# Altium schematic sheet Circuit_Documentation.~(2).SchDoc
size 431 x 279 mm; Date: Not shown in title block; ApprovedBy: Not shown in title block; CheckedBy: Not shown in title block; Author: Not shown in title block; CompanyName: Not shown in title block; Engineer: Not shown in title block; Organization: Not shown in title block; Address1: Not shown in title block; Address2: Not shown in title block; Address3: Not shown in title block; Address4: Not shown in title block; DocumentNumber: 1; Revision: Use project parameter SCH_Rev; SheetNumber: 1; SheetTotal: 2; PageSetup: Record=PageOptions¦CenterHorizontal=True¦CenterVertical=True¦PrintScale=1.00¦XCorrection=1.00¦YCorrection=1.00¦PrintKind=0¦BorderSize=5000000¦LeftOffset=0¦BottomOffset=0¦Orientation=2¦PaperLength=1000¦PaperWidth=1000¦Scale=100¦PaperSource=15¦PrintQuality=600¦MediaType=1¦DitherType=10¦PaperKind=Letter¦PrintScaleMode=1
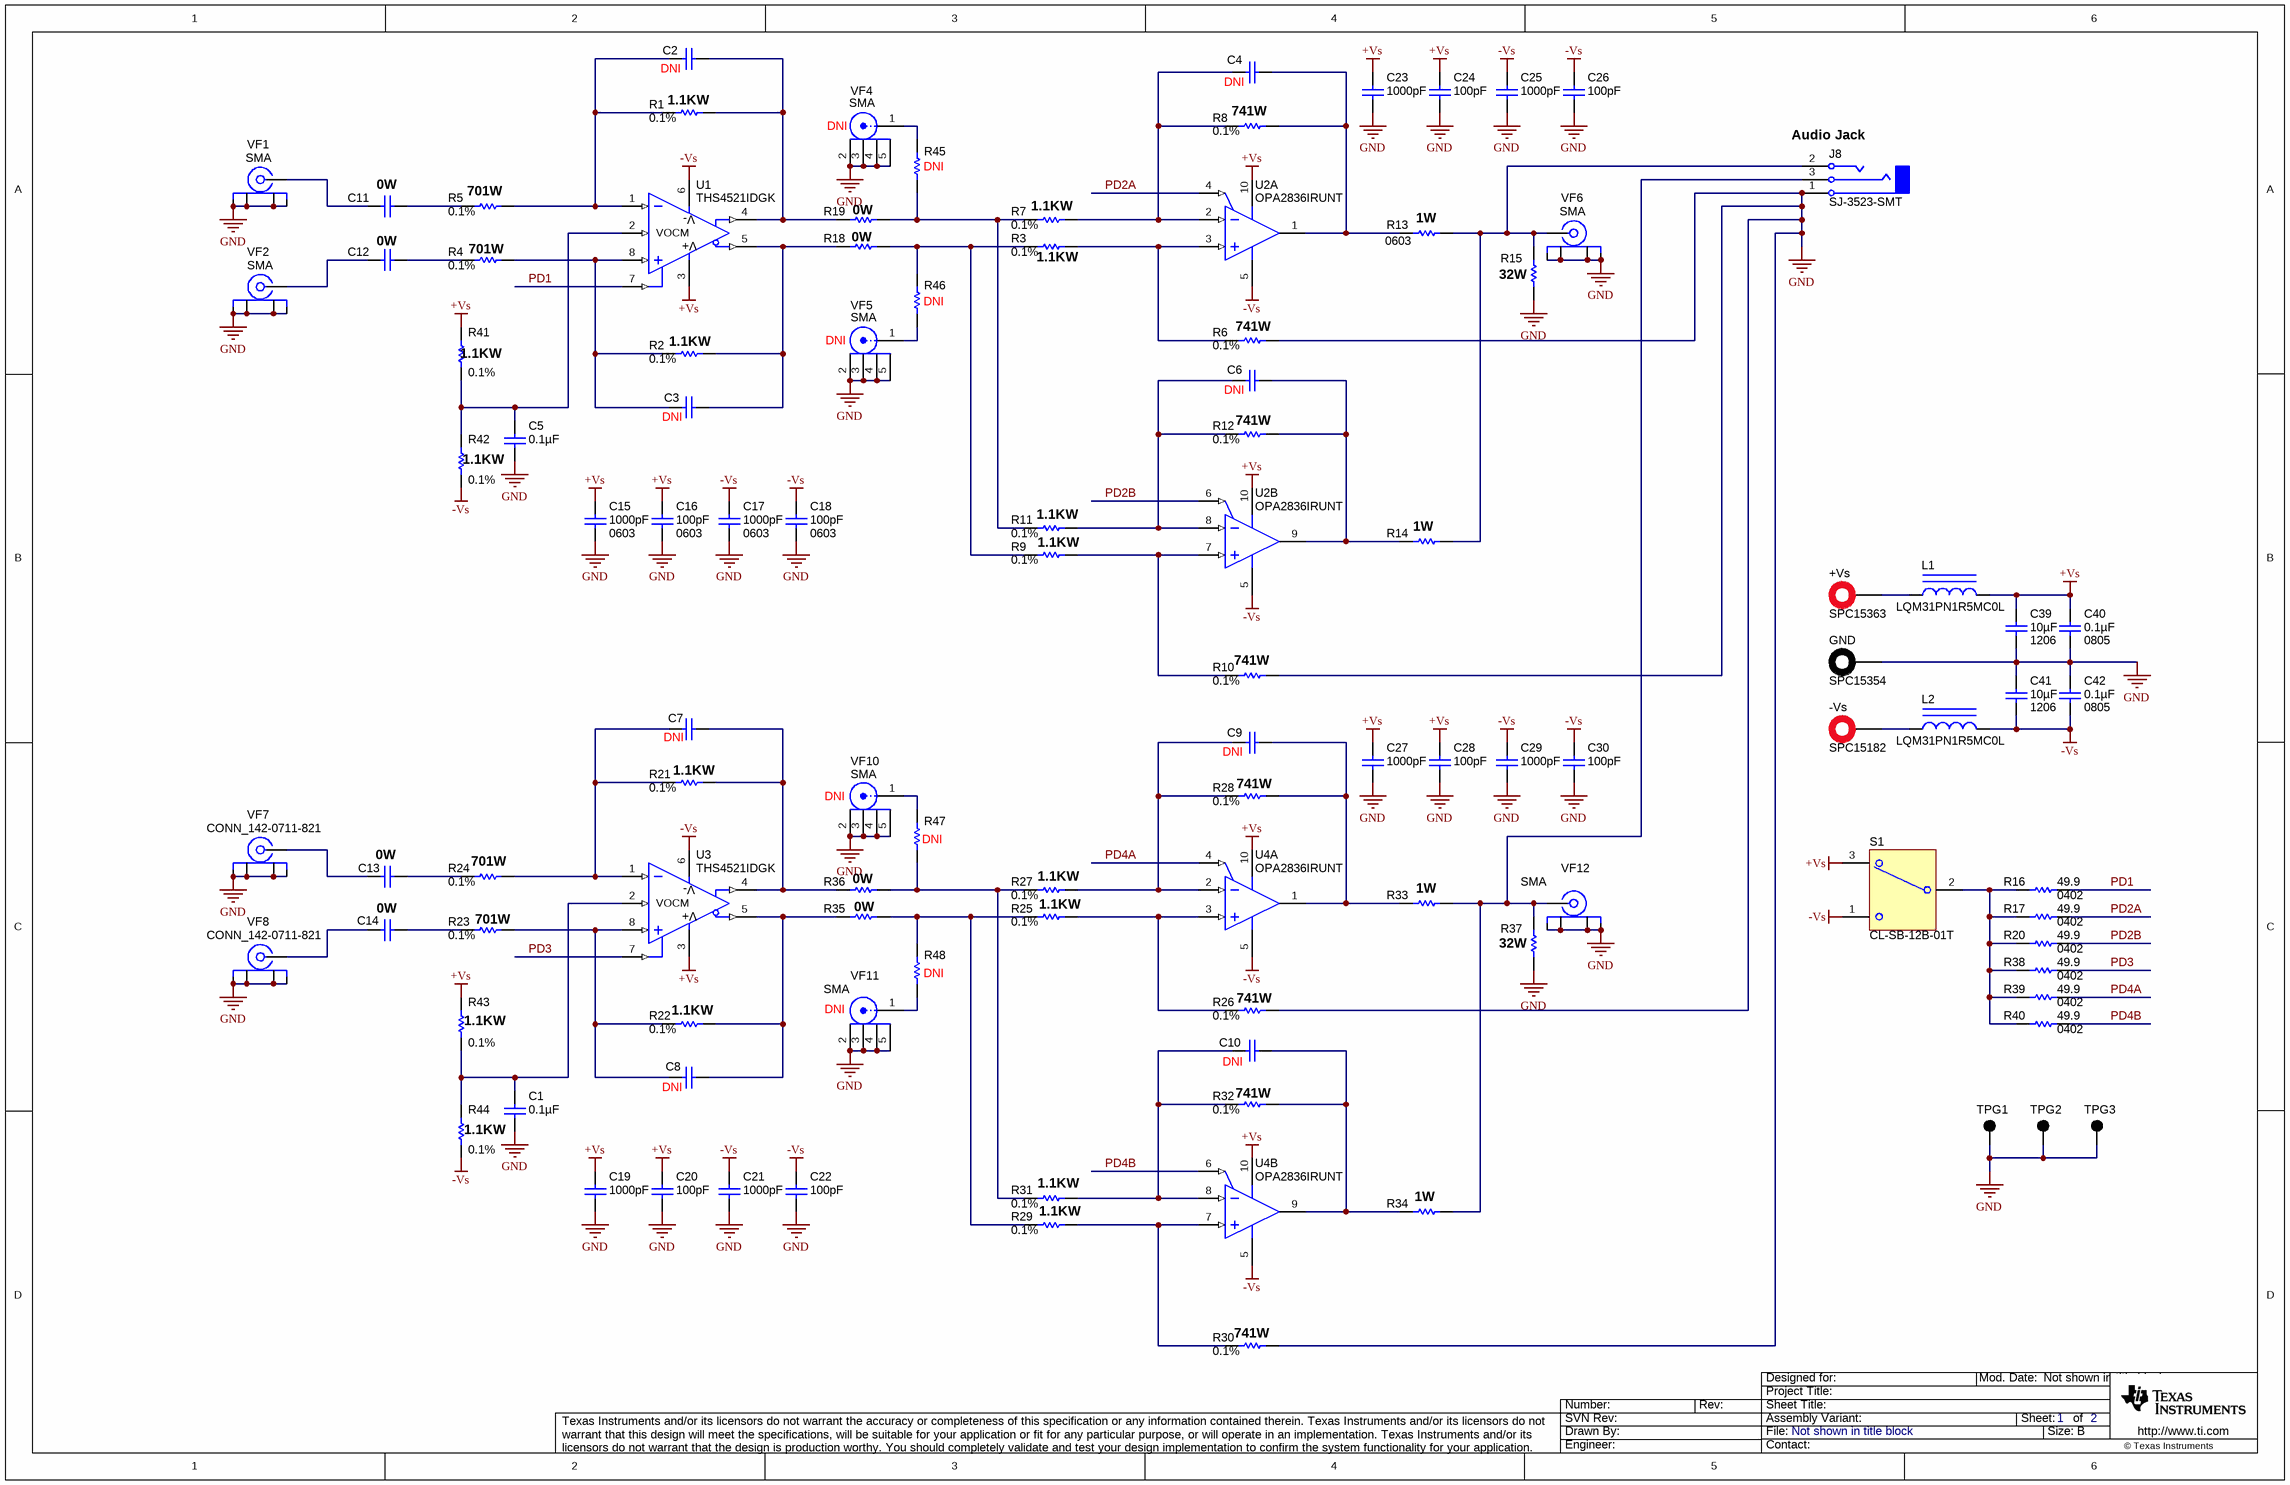
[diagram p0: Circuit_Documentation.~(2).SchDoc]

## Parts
+Vs  SPC15363  [Tenma_SPC15363]
-Vs  SPC15182  [Tenma_SPC15363]
C1  ValueDisplayed: 0.1µF  [0603L]  (hidden comment: C1608X7R1H104K)
C2  (no value)  [0402L]
C3  (no value)  [0402L]
C4  (no value)  [0402L]
C5  ValueDisplayed: 0.1µF  [0603L]  (hidden comment: C1608X7R1H104K)
C6  (no value)  [0402L]
C7  (no value)  [0402L]
C8  (no value)  [0402L]
C9  (no value)  [0402L]
C10  (no value)  [0402L]
C11  (no value)  [1206L]
C12  (no value)  [1206L]
C13  (no value)  [1206L]
C14  (no value)  [1206L]
C15  ValueDisplayed: 1000pF  PackageReference: 0603  [0603L]  (hidden comment: C1608C0G1H102J)
C16  ValueDisplayed: 100pF  PackageReference: 0603  [0603L]  (hidden comment: 06035A101JAT2A)
C17  ValueDisplayed: 1000pF  PackageReference: 0603  [0603L]  (hidden comment: C1608C0G1H102J)
C18  ValueDisplayed: 100pF  PackageReference: 0603  [0603L]  (hidden comment: 06035A101JAT2A)
C19  ValueDisplayed: 1000pF  [0603L]  (hidden comment: C1608C0G1H102J)
C20  ValueDisplayed: 100pF  [0603L]  (hidden comment: 06035A101JAT2A)
C21  ValueDisplayed: 1000pF  [0603L]  (hidden comment: C1608C0G1H102J)
C22  ValueDisplayed: 100pF  [0603L]  (hidden comment: 06035A101JAT2A)
C23  ValueDisplayed: 1000pF  [0402L]  (hidden comment: C1005C0G1E102J)
C24  ValueDisplayed: 100pF  [0402L]  (hidden comment: CC0402JRNPO9BN101)
C25  ValueDisplayed: 1000pF  [0402L]  (hidden comment: C1005C0G1E102J)
C26  ValueDisplayed: 100pF  [0402L]  (hidden comment: CC0402JRNPO9BN101)
C27  ValueDisplayed: 1000pF  [0402L]  (hidden comment: C1005C0G1E102J)
C28  ValueDisplayed: 100pF  [0402L]  (hidden comment: CC0402JRNPO9BN101)
C29  ValueDisplayed: 1000pF  [0402L]  (hidden comment: C1005C0G1E102J)
C30  ValueDisplayed: 100pF  [0402L]  (hidden comment: CC0402JRNPO9BN101)
C39  ValueDisplayed: 10µF  PackageReference: 1206  [1206L]  (hidden comment: GRM31CR61E106KA12L)
C40  ValueDisplayed: 0.1µF  PackageReference: 0805  [0805L]  (hidden comment: 08055C104KAT2A)
C41  ValueDisplayed: 10µF  PackageReference: 1206  [1206L]  (hidden comment: GRM31CR61E106KA12L)
C42  ValueDisplayed: 0.1µF  PackageReference: 0805  [0805L]  (hidden comment: 08055C104KAT2A)
GND  SPC15354  [Tenma_SPC15354]
J8  SJ-3523-SMT  [CUI_SJ-3523-SMT]
L1  LQM31PN1R5MC0L  [1206L]
L2  LQM31PN1R5MC0L  [1206L]
R1  Value1: 0.1%  [0603L]  (hidden comment: RT0603BRD071K11L)
R2  Value1: 0.1%  [0603L]  (hidden comment: RT0603BRD071K11L)
R3  Value1: 0.1%  [0603L]  (hidden comment: RT0603BRD071K11L)
R4  Value1: 0.1%  [0603L]  (hidden comment: RT0603BRD07741RL)
R5  Value1: 0.1%  [0603L]  (hidden comment: RT0603BRD07741RL)
R6  Value1: 0.1%  [0603L]  (hidden comment: RT0603BRD071K11L)
R7  Value1: 0.1%  [0603L]  (hidden comment: RT0603BRD071K11L)
R8  Value1: 0.1%  [0603L]  (hidden comment: RT0603BRD071K11L)
R9  Value1: 0.1%  [0603L]  (hidden comment: RT0603BRD071K11L)
R10  Value1: 0.1%  [0603L]  (hidden comment: RT0603BRD071K11L)
R11  Value1: 0.1%  [0603L]  (hidden comment: RT0603BRD071K11L)
R12  Value1: 0.1%  [0603L]  (hidden comment: RT0603BRD071K11L)
R13  PackageReference: 0603  [0603L]  (hidden comment: CRCW06031R00JNEA)
R14  CRCW06031R00JNEA  [0603L]  (value not drawn)
R15  CRCW120632R4FKEA  [1206L]  (value not drawn)
R16  ValueDisplayed: 49.9  PackageReference: 0402  [0402L]  (hidden comment: CRCW040249R9FKED)
R17  ValueDisplayed: 49.9  PackageReference: 0402  [0402L]  (hidden comment: CRCW040249R9FKED)
R18  CRCW06030000Z0EA  [0603L]  (value not drawn)
R19  CRCW06030000Z0EA  [0603L]  (value not drawn)
R20  ValueDisplayed: 49.9  PackageReference: 0402  [0402L]  (hidden comment: CRCW040249R9FKED)
R21  Value1: 0.1%  [0603L]  (hidden comment: RT0603BRD071K11L)
R22  Value1: 0.1%  [0603L]  (hidden comment: RT0603BRD071K11L)
R23  Value1: 0.1%  [0603L]  (hidden comment: RT0603BRD07741RL)
R24  Value1: 0.1%  [0603L]  (hidden comment: RT0603BRD07741RL)
R25  Value1: 0.1%  [0603L]  (hidden comment: RT0603BRD071K11L)
R26  Value1: 0.1%  [0603L]  (hidden comment: RT0603BRD071K11L)
R27  Value1: 0.1%  [0603L]  (hidden comment: RT0603BRD071K11L)
R28  Value1: 0.1%  [0603L]  (hidden comment: RT0603BRD071K11L)
R29  Value1: 0.1%  [0603L]  (hidden comment: RT0603BRD071K11L)
R30  Value1: 0.1%  [0603L]  (hidden comment: RT0603BRD071K11L)
R31  Value1: 0.1%  [0603L]  (hidden comment: RT0603BRD071K11L)
R32  Value1: 0.1%  [0603L]  (hidden comment: RT0603BRD071K11L)
R33  CRCW06031R00JNEA  [0603L]  (value not drawn)
R34  CRCW06031R00JNEA  [0603L]  (value not drawn)
R35  CRCW06030000Z0EA  [0603L]  (value not drawn)
R36  CRCW06030000Z0EA  [0603L]  (value not drawn)
R37  CRCW120632R4FKEA  [1206L]  (value not drawn)
R38  ValueDisplayed: 49.9  PackageReference: 0402  [0402L]  (hidden comment: CRCW040249R9FKED)
R39  ValueDisplayed: 49.9  PackageReference: 0402  [0402L]  (hidden comment: CRCW040249R9FKED)
R40  ValueDisplayed: 49.9  PackageReference: 0402  [0402L]  (hidden comment: CRCW040249R9FKED)
R41  Value1: 0.1%  [0603L]  (hidden comment: RT0603BRD071K11L)
R42  Value1: 0.1%  [0603L]  (hidden comment: RT0603BRD071K11L)
R43  Value1: 0.1%  [0603L]  (hidden comment: RT0603BRD071K11L)
R44  Value1: 0.1%  [0603L]  (hidden comment: RT0603BRD071K11L)
R45  CRCW04020000Z0ED  [0402L]  (value not drawn)
R46  CRCW04020000Z0ED  [0402L]  (value not drawn)
R47  CRCW04020000Z0ED  [0402L]  (value not drawn)
R48  CRCW04020000Z0ED  [0402L]  (value not drawn)
S1  CL-SB-12B-01T  [SW_CL-SB-12B-01]
TPG1  5011  [Keystone5011]  (value not drawn)
TPG2  5011  [Keystone5011]  (value not drawn)
TPG3  5011  [Keystone5011]  (value not drawn)
U1  THS4521IDGK  [DGK0008A_N]
U2  OPA2836IRUNT  [RUN0010A]  (parts A,B of 2)
U3  THS4521IDGK  [DGK0008A_N]
U4  OPA2836IRUNT  [RUN0010A]  (parts A,B of 2)
VF1  SMA  [CONN_142-0711-821]
VF2  SMA  [CONN_142-0711-821]
VF4  SMA  [Johnson_142-0701-20x]
VF5  SMA  [Johnson_142-0701-20x]
VF6  SMA  [CONN_142-0711-821]
VF7  CONN_142-0711-821  [CONN_142-0711-821]
VF8  CONN_142-0711-821  [CONN_142-0711-821]
VF10  SMA  [Johnson_142-0701-20x]
VF11  SMA  [Johnson_142-0701-20x]
VF12  SMA  [CONN_142-0711-821]

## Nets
+Vs: C15.1 C16.1 C19.1 C20.1 C23.1 C24.1 C27.1 C28.1 C39.1 C40.1 L1.2 R41.2 R43.2 S1.3 U1.3(VS+) U2.10(VS+) U3.3(VS+) U4.10(VS+)
-Vs: C17.1 C18.1 C21.1 C22.1 C25.1 C26.1 C29.1 C30.1 C41.2 C42.2 L2.2 R42.1 R44.1 S1.1 U1.6(VS-) U2.5(VS-) U3.6(VS-) U4.5(VS-)
GND: C1.2 C5.2 C15.2 C16.2 C17.2 C18.2 C19.2 C20.2 C21.2 C22.2 C23.2 C24.2 C25.2 C26.2 C27.2 C28.2 C29.2 C30.2 C39.2 C40.2 C41.1 C42.1 GND.1 J8.1(SLEEVE) R6.2 R10.2 R15.1 R26.2 R30.2 R37.1 TPG1.1 TPG2.1 TPG3.1 VF1.2(GND) VF1.3(GND) VF1.4 VF1.5(GND) VF2.2(GND) VF2.3(GND) VF2.4 VF2.5(GND) VF4.2 VF4.3 VF4.4 VF4.5 VF5.2 VF5.3 VF5.4 VF5.5 VF6.2(GND) VF6.3(GND) VF6.4 VF6.5(GND) VF7.2(GND) VF7.3(GND) VF7.4 VF7.5(GND) VF8.2(GND) VF8.3(GND) VF8.4 VF8.5(GND) VF10.2 VF10.3 VF10.4 VF10.5 VF11.2 VF11.3 VF11.4 VF11.5 VF12.2(GND) VF12.3(GND) VF12.4 VF12.5(GND)
PD1: R16.2 U1.7(~{PD})
PD2A: R17.2 U2.4(~{PD1})
PD2B: R20.2 U2.6(~{PD2})
PD3: R38.2 U3.7(~{PD})
PD4A: R39.2 U4.4(~{PD1})
PD4B: R40.2 U4.6(~{PD2})
Net+Vs_1: +Vs.1 L1.1
Net-Vs_1: -Vs.1 L2.1
NetC1_1: C1.1 R43.1 R44.2 U3.2(VOCM)
NetC2_1: C2.1 R1.2 R19.1 U1.4(VOUT+)
NetC2_2: C2.2 R1.1 R5.2 U1.1(VIN-)
NetC3_1: C3.1 R2.2 R18.1 U1.5(VOUT-)
NetC3_2: C3.2 R2.1 R4.2 U1.8(VIN+)
NetC4_1: C4.1 R8.2 R13.1 U2.1(VOUT1)
NetC4_2: C4.2 R7.2 R8.1 U2.2(VIN1-)
NetC5_1: C5.1 R41.1 R42.2 U1.2(VOCM)
NetC6_1: C6.1 R12.2 R14.1 U2.9(VOUT2)
NetC6_2: C6.2 R11.2 R12.1 U2.8(VIN2-)
NetC7_1: C7.1 R21.2 R36.1 U3.4(VOUT+)
NetC7_2: C7.2 R21.1 R24.2 U3.1(VIN-)
NetC8_1: C8.1 R22.2 R35.1 U3.5(VOUT-)
NetC8_2: C8.2 R22.1 R23.2 U3.8(VIN+)
NetC9_1: C9.1 R28.2 R33.1 U4.1(VOUT1)
NetC9_2: C9.2 R27.2 R28.1 U4.2(VIN1-)
NetC10_1: C10.1 R32.2 R34.1 U4.9(VOUT2)
NetC10_2: C10.2 R31.2 R32.1 U4.8(VIN2-)
NetC11_1: C11.1 R5.1
NetC11_2: C11.2 VF1.1(SIGNAL)
NetC12_1: C12.1 R4.1
NetC12_2: C12.2 VF2.1(SIGNAL)
NetC13_1: C13.1 R24.1
NetC13_2: C13.2 VF7.1(SIGNAL)
NetC14_1: C14.1 R23.1
NetC14_2: C14.2 VF8.1(SIGNAL)
NetJ8_2: J8.2(TIP) R13.2 R14.2 R15.2 VF6.1(SIGNAL)
NetJ8_3: J8.3(RING) R33.2 R34.2 R37.2 VF12.1(SIGNAL)
NetR3_1: R3.1 R9.1 R18.2 R46.2
NetR3_2: R3.2 R6.1 U2.3(VIN1+)
NetR7_1: R7.1 R11.1 R19.2 R45.1
NetR9_2: R9.2 R10.1 U2.7(VIN2+)
NetR16_1: R16.1 R17.1 R20.1 R38.1 R39.1 R40.1 S1.2(COM)
NetR25_1: R25.1 R29.1 R35.2 R48.2
NetR25_2: R25.2 R26.1 U4.3(VIN1+)
NetR27_1: R27.1 R31.1 R36.2 R47.1
NetR29_2: R29.2 R30.1 U4.7(VIN2+)
NetR45_2: R45.2 VF4.1
NetR46_1: R46.1 VF5.1
NetR47_2: R47.2 VF10.1
NetR48_1: R48.1 VF11.1

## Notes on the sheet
- (near C2) DNI
- (near R1) 1.1KW
- (near C4) DNI
- (near VF4) DNI
- (near R45) DNI
- (near R8) 741W
- (near J8) Audio Jack
- (near C11) 0W
- (near R5) 701W
- (near R18) 0W
- (near R19) 0W
- (near R7) 1.1KW
- (near R13) 1W
- (near C12) 0W
- (near R4) 701W
- (near R46) DNI
- (near R3) 1.1KW
- (near R15) 32W
- (near R41) 1.1KW
- (near R2) 1.1KW
- (near VF5) DNI
- (near R6) 741W
- (near C3) DNI
- (near C6) DNI
- (near R12) 741W
- (near R42) 1.1KW
- (near R11) 1.1KW
- 1.1KW
- (near R14) 1W
- (near R10) 741W
- (near C7) DNI
- (near R21) 1.1KW
- (near C9) DNI
- (near VF10) DNI
- (near R47) DNI
- (near R28) 741W
- (near C13) 0W
- 0W
- (near R24) 701W
- (near R36) 0W
- (near R35) 0W
- (near R27) 1.1KW
- (near R33) 1W
- (near R23) 701W
- (near R48) DNI
- (near R37) 32W
- (near R43) 1.1KW
- (near R22) 1.1KW
- (near VF11) DNI
- (near R26) 741W
- (near C8) DNI
- (near C10) DNI
- (near R32) 741W
- (near R31) 1.1KW
- (near R34) 1W
- (near R30) 741W

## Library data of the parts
+Vs = SPC15363: BANANA JACK, SOLDER LUG, RED, TH; Manufacturer: Tenma; SymbolCreator: a0412235; U/M: EA
-Vs = SPC15363: BANANA JACK, SOLDER LUG, GREEN, TH; Manufacturer: Tenma; SymbolCreator: a0412235; U/M: EA
C1 C5 = C1608X7R1H104K: CAP, CERM, 0.1 µF, 50 V, +/- 10%, X7R, 0603; Manufacturer: TDK; Polarized: N; CompType: Capacitor; Value: 0.1uF; U/M: EA; Cap_F: 0.0000001; Tolerance_%: 10; ESR_ohm: 0.017; Value1: 0.017 ohm; VDC_V: 50; Value2: 50V; TaMin_C: -55; TaMax_C: 125; Cap_Case: 0603
C2-C4 C6-C14 = Capacitor: CAP, CERM, xxxF, xxV, [TempCo], xx%, [PackageReference]; Manufacturer: Used in BOM report; Polarized: N; U/M: EA
C15 C17 = C1608C0G1H102J: CAP, CERM, 1000 pF, 50 V, +/- 5%, C0G/NP0, 0603; Manufacturer: TDK; Polarized: N; CompType: Capacitor; Value: 1000pF; U/M: EA; Cap_F: 0.000000001; Tolerance_%: 5; ESR_ohm: 0.0563; Value1: 0.0563 ohm; VDC_V: 50; Value2: 50V; TaMin_C: -55; TaMax_C: 125
C16 C18 = 06035A101JAT2A: CAP, CERM, 100 pF, 50 V, +/- 5%, C0G/NP0, 0603; Manufacturer: AVX; Polarized: N; CompType: Capacitor; Value: 100pF; U/M: EA; Cap_F: 0.0000000001; Tolerance_%: 5; ESR_ohm: 0.119; Value1: 0.119 ohm; VDC_V: 50; Value2: 50V; TaMin_C: -55; TaMax_C: 125
C19 C21 = C1608C0G1H102J: CAP, CERM, 1000 pF, 50 V, +/- 5%, C0G/NP0, 0603; Manufacturer: TDK; Polarized: N; CompType: Capacitor; Value: 1000pF; U/M: EA; Cap_F: 0.000000001; Tolerance_%: 5; ESR_ohm: 0.0563; Value1: 0.0563 ohm; VDC_V: 50; Value2: 50V; TaMin_C: -55; TaMax_C: 125; Cap_Case: 0603
C20 C22 = 06035A101JAT2A: CAP, CERM, 100 pF, 50 V, +/- 5%, C0G/NP0, 0603; Manufacturer: AVX; Polarized: N; CompType: Capacitor; Value: 100pF; U/M: EA; Cap_F: 0.0000000001; Tolerance_%: 5; ESR_ohm: 0.119; Value1: 0.119 ohm; VDC_V: 50; Value2: 50V; TaMin_C: -55; TaMax_C: 125; Cap_Case: 0603
C23 C25 C27 C29 = C1005C0G1E102J: CAP, CERM, 1000 pF, 25 V, +/- 5%, C0G/NP0, 0402; Manufacturer: TDK; Polarized: N; CompType: Capacitor; Value: 1000pF; U/M: EA; Cap_F: 0.000000001; Tolerance_%: 5; Value1: Unknown; VDC_V: 25; Value2: 25V; TaMin_C: -55; TaMax_C: 125; Cap_Case: 0402
C24 C26 C28 C30 = CC0402JRNPO9BN101: CAP, CERM, 100 pF, 50 V, +/- 5%, C0G/NP0, 0402; Manufacturer: Yageo America; Polarized: N; CompType: Capacitor; Value: 100pF; U/M: EA; Cap_F: 0.0000000001; Tolerance_%: 5; Value1: Unknown; VDC_V: 50; Value2: 50V; TaMin_C: -55; TaMax_C: 125; Cap_Case: 0402
C39 C41 = GRM31CR61E106KA12L: CAP, CERM, 10 µF, 25 V, +/- 10%, X5R, 1206; Manufacturer: MuRata; Polarized: N; CompType: Capacitor; Value: 10uF; U/M: EA; Cap_F: 0.00001; Tolerance_%: 10; ESR_ohm: 0.004; Value1: 0.004 ohm; VDC_V: 25; Value2: 25V; TaMin_C: -55; TaMax_C: 85
C40 C42 = 08055C104KAT2A: CAP, CERM, 0.1 µF, 50 V, +/- 10%, X7R, 0805; Manufacturer: AVX; Polarized: N; CompType: Capacitor; Value: 0.1uF; U/M: EA; Cap_F: 0.0000001; Tolerance_%: 10; ESR_ohm: 0.024; Value1: 0.024 ohm; VDC_V: 50; Value2: 50V; TaMin_C: -55; TaMax_C: 125
GND = SPC15354: BANANA JACK, SOLDER LUG, BLACK, TH; Manufacturer: Tenma; SymbolCreator: a0412235; U/M: EA
J8 = SJ-3523-SMT: Audio Jack, 3.5mm, Stereo, R/A, SMT; Manufacturer: CUI Inc.; SymbolCreator: a0412235; U/M: EA
L1 L2 = LQM31PN1R5MC0L: Inductor, Multilayer, Ferrite, 1.5 µH, 1 A, 0.17 ohm, SMD; Manufacturer: MuRata; Value: 1.5uH; Ind_H: 1.5E-6; ValueDisplayed: 1.5µH; Imax_A: 1; Irms: 1A @ 40C rise; DCR_ohm: 0.17; Value2: 1A
R1-R3 R6-R12 R21 R22 R25-R32 R41-R44 = RT0603BRD071K11L: RES, 1.11 k, 0.1%, 0.1 W, 0603; Manufacturer: Yageo America; CompType: Resistor; Value: 1.11k; Res_ohm: 1110; Value_Code: 1k11; Tolerance_%: 0.1; Value2: 0.1W; VDC_V: 75; TempCo: 25 ppm/C; EIA_Code: E192; U/M: EA
R4 R5 R23 R24 = RT0603BRD07741RL: RES, 741, 0.1%, 0.1 W, 0603; Manufacturer: Yageo America; CompType: Resistor; Value: 741; Value_Code: 741R; Tolerance_%: 0.1; Value2: 0.1W; VDC_V: 75; TempCo: 25 ppm/C; EIA_Code: E192; U/M: EA
R13 R14 R33 R34 = CRCW06031R00JNEA: RES, 1.0, 5%, 0.1 W, 0603; Manufacturer: Vishay-Dale; CompType: Resistor; Value: 1.0; Res_ohm: 1; Value_Code: 1R00; Tolerance_%: 5; Power_W: 0.1; Value2: 0.1W; VDC_V: 75; TempCo: 200 ppm/C; EIA_Code: E24; U/M: EA
R15 R37 = CRCW120632R4FKEA: RES, 32.4, 1%, 0.25 W, 1206; Manufacturer: Vishay-Dale; CompType: Resistor; Value: 32.4; Value_Code: 32R4; Tolerance_%: 1; Power_W: 0.25; Value2: 0.25W; VDC_V: 200; TempCo: 100 ppm/C; EIA_Code: E96; U/M: EA
R16 R17 R20 R38-R40 = CRCW040249R9FKED: RES, 49.9, 1%, 0.063 W, 0402; Manufacturer: Vishay-Dale; CompType: Resistor; Value: 49.9; Value_Code: 49R9; Tolerance_%: 1; Power_W: 0.063; Value2: 0.063W; VDC_V: 50; TempCo: 100 ppm/C; EIA_Code: E96; U/M: EA
R18 R19 R35 R36 = CRCW06030000Z0EA: RES, 0, 5%, 0.1 W, 0603; Manufacturer: Vishay-Dale; CompType: Resistor; Value: 0; Value_Code: 0000; Tolerance_%: 5; Power_W: 0.1; Value2: 0.1W; VDC_V: 75; TempCo: 200 ppm/C; EIA_Code: E24; U/M: EA
R45-R48 = CRCW04020000Z0ED: RES, 0, 5%, 0.063 W, 0402; Manufacturer: Vishay-Dale; CompType: Resistor; Value: 0; Value_Code: 0000; Tolerance_%: 5; Power_W: 0.063; Value2: 0.063W; VDC_V: 50; TempCo: 200 ppm/C; EIA_Code: E24; U/M: EA
S1 = CL-SB-12B-01T: Switch, Slide, SPDT, 0.2A, GULL, 12V, SMD; Manufacturer: Copal Electronics; SymbolCreator: x0208326; VDC_V: 12; SwitchFunction: On-On; PositionCount: 2; CurrentRating_mA: 200
TPG1-TPG3 = 5011: Test Point, Multipurpose, Black, TH; Manufacturer: Keystone; CompType: Test Point Loop; U/M: EA
U1 U3 = THS4521IDGK: VERY LOW POWER, NEGATIVE RAIL INPUT, RAIL-TO-RAIL OUTPUT, FULLY DIFFERENTIAL AMPLIFIER, DGK0008A; Manufacturer: Texas Instruments; SymbolCreator: a0411947; CompType: IC; U/M: EA
U2 U4 = OPA2836IRUNT: Dual, Very Low Power, Rail to Rail Out, Negative Rail In, VFB Operational Amplifier, 2.5 to 5.5 V, -40 to 85 degC, 10-pin QFN (RUN0010A), Green (RoHS & no Sb/Br); Manufacturer: Texas Instruments; Alternate Manufacturer: None; Alternate PartNumber: Equivalent; 2nd Harmonic(dBc): 85; 3rd Harmonic(dBc): 105; Acl, min stable gain(V/V): 1; BW @ Acl(MHz): 205; Iib(Max)(nA): 1550; Io(Typ)(mA): 50; Iq per channel(Max)(mA): 1.2; Number of Channels: 2; Settling Time (0.1%)(Typ)(ns): 30; Slew Rate(Typ)(V/us): 560; Sub Family: High Output Current Amplifier (>=50mA), High Speed Amplifier (>=50MHz), Low Noise Amp (<=10nV/rtHz), Low Offset Voltage Amplifier (<=500uV), Low Supply Voltage Amplifier (<=2.7V); THD (Fc is 1 MHz)(Typ)(dB): -130; Vio(Max)(mV): 0.4; Vn at Flatband(Typ)(nV/rtHz): 4.6; Vs(Max)(V): 5.5; Vs(Min)(V): 2.5
VF1 VF2 VF6-VF8 VF12 = CONN_142-0711-821: CONNECTOR, SHEILDED, END LAUNCH JACK, GOLD PLATED, FOR 0.062 PCB, EDGE MOUNTED; Manufacturer: Cinch Connectivity Solutions Johnson; area: 95000
VF4 VF5 VF10 VF11 = 142-0701-201: Connector, TH, SMA; Manufacturer: Emerson Network Power; SymbolCreator: X0208326; U/M: EA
